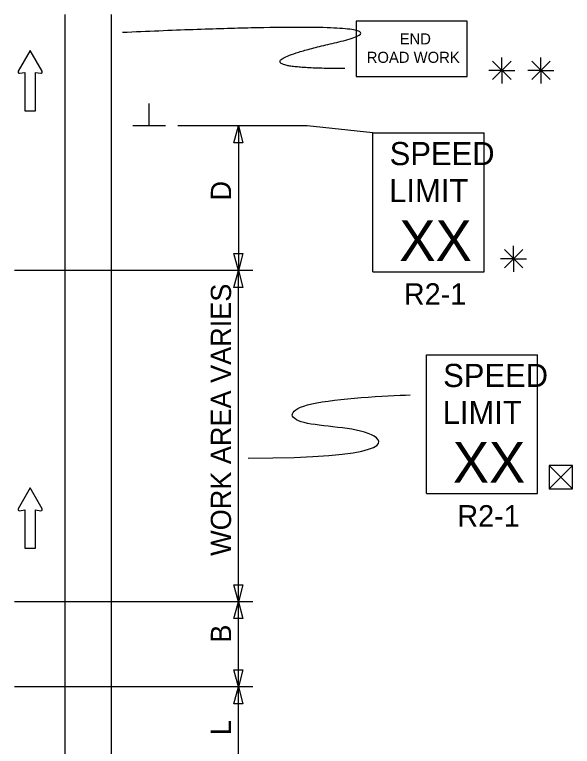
# Model space of a CAD drawing. Extents: x 16553 to 18478, y 5759 to 7026.
# Drawn here: x 16942.3 to 17135.1, y 6673.6 to 6926.7 of the extents above; entities that cross this region are included whole.
import ezdxf

# ---------------------------------------------------------------- set-up
doc = ezdxf.new("R2010")
doc.units = 0
for name, color, linetype in [('MT_SCRATCH_LEVEL_E', 7, 'Continuous'), ('PAVT_EDGE_EX', 7, 'Continuous'), ('TRAFFIC_SIGNS_PR', 7, 'Continuous'), ('TYPICAL_TEXT_DIMEN_PR', 7, 'Continuous')]:
    doc.layers.add(name, color=color, linetype=linetype)

msp = doc.modelspace()

# ---------------------------------------------------------------- linework, layer by layer
at = {"layer": 'MT_SCRATCH_LEVEL_E'}
for p, q in [((16947.62, 6914.3), (16943.51, 6907.06)), ((16951.77, 6907.06), (16947.62, 6914.3)), ((16943.99, 6906.37), (16945.77, 6906.69)), ((16945.77, 6906.69), (16945.77, 6893.43)), ((16949.51, 6893.43), (16949.51, 6906.69)), ((16949.51, 6906.69), (16951.29, 6906.37)), ((16945.77, 6893.43), (16949.51, 6893.43)), ((16947.62, 6763.02), (16943.51, 6755.78)), ((16951.77, 6755.78), (16947.62, 6763.02)), ((16943.99, 6755.1), (16945.77, 6755.41)), ((16945.77, 6755.41), (16945.77, 6742.15)), ((16949.51, 6742.15), (16949.51, 6755.41)), ((16949.51, 6755.41), (16951.29, 6755.1)), ((16945.77, 6742.15), (16949.51, 6742.15))]:
    msp.add_line(p, q, dxfattribs=at)
for centre, start, end in [((16943.92, 6906.83), 150.4248, 279.9638), ((16951.36, 6906.83), 260.0362, 29.7731), ((16943.92, 6755.56), 150.4248, 279.9638), ((16951.36, 6755.56), 260.0362, 29.7731)]:
    msp.add_arc(centre, 0.463, start, end, dxfattribs=at)
at = {"layer": 'PAVT_EDGE_EX'}
for p, q in [((16959.66, 6926.66), (16959.66, 6267.34)), ((16975.66, 6926.66), (16975.66, 6267.34))]:
    msp.add_line(p, q, dxfattribs=at)
at = {"layer": 'TRAFFIC_SIGNS_PR'}
for p, q in [((17066.18, 6885.75), (17104.58, 6885.75)), ((17066.18, 6837.75), (17066.18, 6885.75)), ((17104.58, 6837.75), (17104.58, 6885.75)), ((17066.18, 6837.75), (17104.58, 6837.75)), ((17084.68, 6809.02), (17123.08, 6809.02)), ((17084.68, 6761.02), (17084.68, 6809.02)), ((17123.08, 6761.02), (17123.08, 6809.02)), ((17084.68, 6761.02), (17123.08, 6761.02))]:
    msp.add_line(p, q, dxfattribs=at)
msp.add_lwpolyline([(17060.4, 6905.24), (17098.8, 6905.24), (17098.8, 6924.44), (17060.4, 6924.44)], close=True, dxfattribs=at)
msp.add_open_spline([(17056.4, 6908), (17013.89, 6908), (17090.41, 6925.41), (16979.62, 6920.47)], degree=2, dxfattribs=at)
at = {"layer": 'TYPICAL_TEXT_DIMEN_PR'}
for p, q in [((17110.74, 6907.37), (17110.74, 6911.82)), ((17124.24, 6907.37), (17124.24, 6911.82)), ((17107.55, 6910.56), (17113.93, 6904.18)), ((17113.93, 6910.56), (17107.55, 6904.18)), ((17121.06, 6910.56), (17127.43, 6904.18)), ((17127.43, 6910.56), (17121.06, 6904.18)), ((17110.74, 6907.37), (17106.21, 6907.37)), ((17110.74, 6907.37), (17113.93, 6907.37)), ((17110.74, 6907.37), (17115.22, 6907.37)), ((17110.74, 6907.37), (17110.74, 6902.87)), ((17124.24, 6907.37), (17119.71, 6907.37)), ((17124.24, 6907.37), (17127.43, 6907.37)), ((17124.24, 6907.37), (17128.72, 6907.37)), ((17124.24, 6907.37), (17124.24, 6902.87)), ((16988.79, 6888.16), (16988.79, 6895.95)), ((16994.41, 6888.16), (16983.16, 6888.16)), ((17043.4, 6888.16), (16998.66, 6888.16)), ((17018.09, 6882.3), (17019.66, 6888.16)), ((17019.66, 6888.16), (17019.66, 6838.16)), ((17019.66, 6888.16), (17021.23, 6882.3)), ((17066.18, 6885.75), (17043.4, 6888.16)), ((17019.66, 6882.3), (17018.09, 6882.3)), ((17021.23, 6882.3), (17019.66, 6882.3)), ((17111.6, 6845.45), (17117.97, 6839.07)), ((17117.97, 6845.45), (17111.6, 6839.07)), ((17114.79, 6842.26), (17114.79, 6846.71)), ((17019.66, 6838.16), (17018.09, 6844.02)), ((17018.09, 6844.02), (17019.66, 6844.02)), ((17019.66, 6844.02), (17021.23, 6844.02)), ((17021.23, 6844.02), (17019.66, 6838.16)), ((17114.79, 6842.26), (17110.26, 6842.26)), ((17114.79, 6842.26), (17117.97, 6842.26)), ((17114.79, 6842.26), (17119.26, 6842.26)), ((17114.79, 6842.26), (17114.79, 6837.76)), ((17024.66, 6838.16), (16942.27, 6838.16)), ((17018.09, 6832.3), (17019.66, 6838.16)), ((17019.66, 6723.62), (17019.66, 6838.16)), ((17019.66, 6838.16), (17021.23, 6832.3)), ((17019.66, 6832.3), (17018.09, 6832.3)), ((17021.23, 6832.3), (17019.66, 6832.3)), ((17127.12, 6770.69), (17135.12, 6762.69)), ((17127.12, 6762.69), (17135.12, 6770.69)), ((17019.66, 6723.62), (17018.09, 6729.49)), ((17018.09, 6729.49), (17019.66, 6729.49)), ((17019.66, 6729.49), (17021.23, 6729.49)), ((17021.23, 6729.49), (17019.66, 6723.62)), ((17024.66, 6723.62), (16942.27, 6723.62)), ((17018.09, 6717.76), (17019.66, 6723.62)), ((17019.66, 6694.2), (17019.66, 6723.62)), ((17019.66, 6723.62), (17021.23, 6717.76)), ((17019.66, 6717.76), (17018.09, 6717.76)), ((17021.23, 6717.76), (17019.66, 6717.76)), ((17019.66, 6694.2), (17018.09, 6700.06)), ((17018.09, 6700.06), (17019.66, 6700.06)), ((17019.66, 6700.06), (17021.23, 6700.06)), ((17021.23, 6700.06), (17019.66, 6694.2)), ((17024.66, 6694.2), (16942.27, 6694.2)), ((17018.09, 6688.34), (17019.66, 6694.2)), ((17019.66, 6663.63), (17019.66, 6694.2)), ((17019.66, 6694.2), (17021.23, 6688.34)), ((17019.66, 6688.34), (17018.09, 6688.34)), ((17021.23, 6688.34), (17019.66, 6688.34))]:
    msp.add_line(p, q, dxfattribs=at)
msp.add_lwpolyline([(17127.12, 6770.69), (17127.12, 6762.69), (17135.12, 6762.69), (17135.12, 6770.69)], close=True, dxfattribs=at)
msp.add_open_spline([(17022.97, 6773.31), (17071.44, 6773.31), (17071.44, 6784.07), (17036.52, 6784.07), (17036.52, 6793.11), (17070.73, 6794.88), (17079.02, 6795.17)], degree=3, dxfattribs=at)

# ---------------------------------------------------------------- texts
at = {"layer": 'TRAFFIC_SIGNS_PR'}
for s, height, p in [('END', 3.831, (17075.4, 6916.37)), ('ROAD WORK', 3.831, (17064.01, 6909.99)), ('SPEED', 8, (17071.95, 6874.61)), ('LIMIT', 8, (17071.79, 6861.81)), ('XX', 14.031, (17075.29, 6841.51)), ('R2-1', 7.44, (17076.86, 6826.31)), ('SPEED', 8, (17090.44, 6797.88)), ('LIMIT', 8, (17090.28, 6785.08)), ('XX', 14.031, (17093.79, 6764.78)), ('R2-1', 7.44, (17095.35, 6749.58))]:
    msp.add_text(s, height=height, dxfattribs=at).set_placement(p)
at = {"layer": 'TYPICAL_TEXT_DIMEN_PR'}
for s, p in [('D', (17017.1, 6862.38)), ('WORK AREA VARIES', (17017.1, 6739.48)), ('B', (17017.1, 6709.46)), ('L', (17017.1, 6677.49))]:
    msp.add_text(s, height=7, rotation=90, dxfattribs=at).set_placement(p)

doc.saveas('drawing.dxf')
